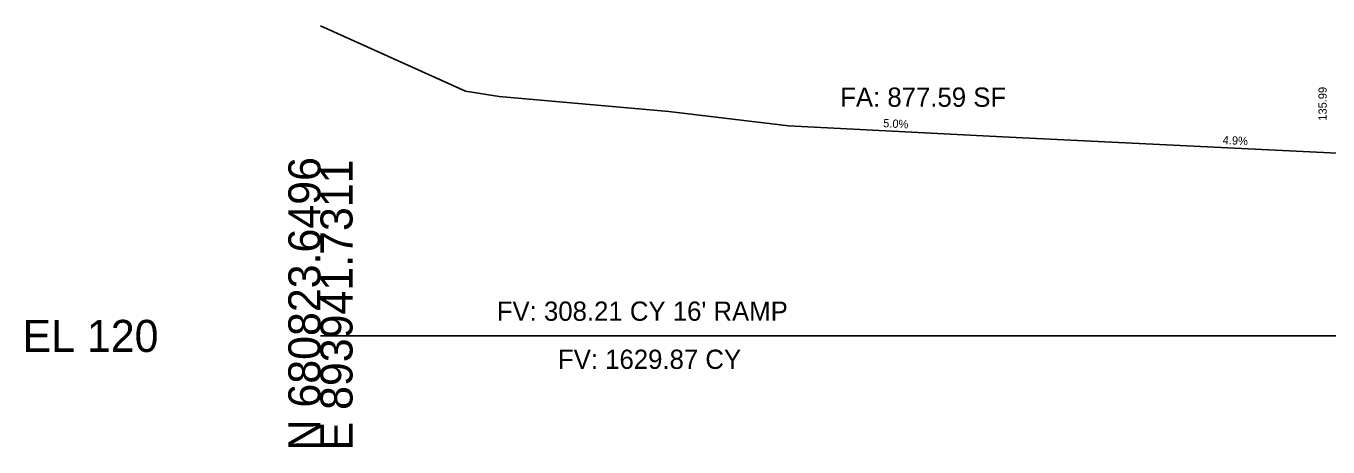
# Model space of a CAD drawing. Extents: x -26 to 4303, y -13 to 10775.
# Drawn here: x 974.3 to 1087.9, y 4490.3 to 4527 of the extents above; entities that cross this region are included whole.
import ezdxf

# ---------------------------------------------------------------- set-up
doc = ezdxf.new("R2010")
doc.units = 0
for name, color, linetype in [('Draft_XS_Grid', 7, 'Continuous'), ('DTM_X_GROUND', 7, 'Continuous'), ('XS_CELL', 7, 'Continuous'), ('XS_M_SHAPES_EARTHWORK', 7, 'Continuous'), ('XS_P_TX_CLEARZONE', 7, 'Continuous'), ('XS_P_TX_FS_BS', 7, 'Continuous'), ('XS_SHEET_EW_TX_VOLUME', 7, 'Continuous')]:
    doc.layers.add(name, color=color, linetype=linetype)

msp = doc.modelspace()

# ---------------------------------------------------------------- linework, layer by layer
at = {"layer": 'DTM_X_GROUND'}
msp.add_lwpolyline([(1000, 4527.05), (1012.65, 4521.36), (1015.59, 4520.9), (1030.41, 4519.59), (1040.86, 4518.33), (1059.52, 4517.39), (1100.05, 4515.4), (1117.74, 4513.76), (1122.89, 4513.42), (1126.76, 4513.63), (1141.7, 4515.78), (1144.7, 4517.14), (1149.91, 4516.83), (1149.96, 4516.83), (1176.71, 4519.61), (1183.12, 4519.79), (1194.2, 4520.77), (1195.63, 4520.84), (1210.28, 4520.77), (1231.86, 4520.75), (1269.14, 4520.53), (1289.17, 4520.49), (1300, 4520.41)], dxfattribs=at)
at = {"layer": 'XS_CELL'}
msp.add_line((1000, 4500), (1150, 4500), dxfattribs=at)

# ---------------------------------------------------------------- texts
at = {"layer": 'Draft_XS_Grid'}
msp.add_text('-', height=0.0001, dxfattribs=at).set_placement((1000, 4500))
at = {"layer": 'XS_CELL'}
for s, p in [('N 680823.6496', (1000, 4490)), ('E 893941.7311', (1002.8, 4490))]:
    msp.add_text(s, height=2.8, rotation=90, dxfattribs=at).set_placement(p)
msp.add_text('EL 120', height=2.8, dxfattribs=at).set_placement((974, 4498.6))
at = {"layer": 'XS_M_SHAPES_EARTHWORK'}
for s, p in [("FV: 308.21 CY 16' RAMP", (1015.39, 4501.32)), ('FV: 1629.87 CY', (1020.73, 4497.12))]:
    msp.add_text(s, height=1.68, dxfattribs=at).set_placement(p)
at = {"layer": 'XS_P_TX_CLEARZONE'}
msp.add_text('135.99', height=0.72, rotation=90, dxfattribs=at).set_placement((1087.82, 4518.79))
msp.add_text('135.99', height=0.72, rotation=90, dxfattribs=at).set_placement((1087.82, 4518.79))
msp.add_text('135.99', height=0.72, rotation=90, dxfattribs=at).set_placement((1087.82, 4518.79))
at = {"layer": 'XS_P_TX_FS_BS'}
for s, rotation, p in [('5.0%', 357.116, (1049.1, 4518.22)), ('4.9%', 357.1857, (1078.73, 4516.75))]:
    msp.add_text(s, height=0.72, rotation=rotation, dxfattribs=at).set_placement(p)
at = {"layer": 'XS_SHEET_EW_TX_VOLUME'}
msp.add_text('FA: 877.59 SF', height=1.68, dxfattribs=at).set_placement((1045.36, 4520))

doc.saveas('drawing.dxf')
